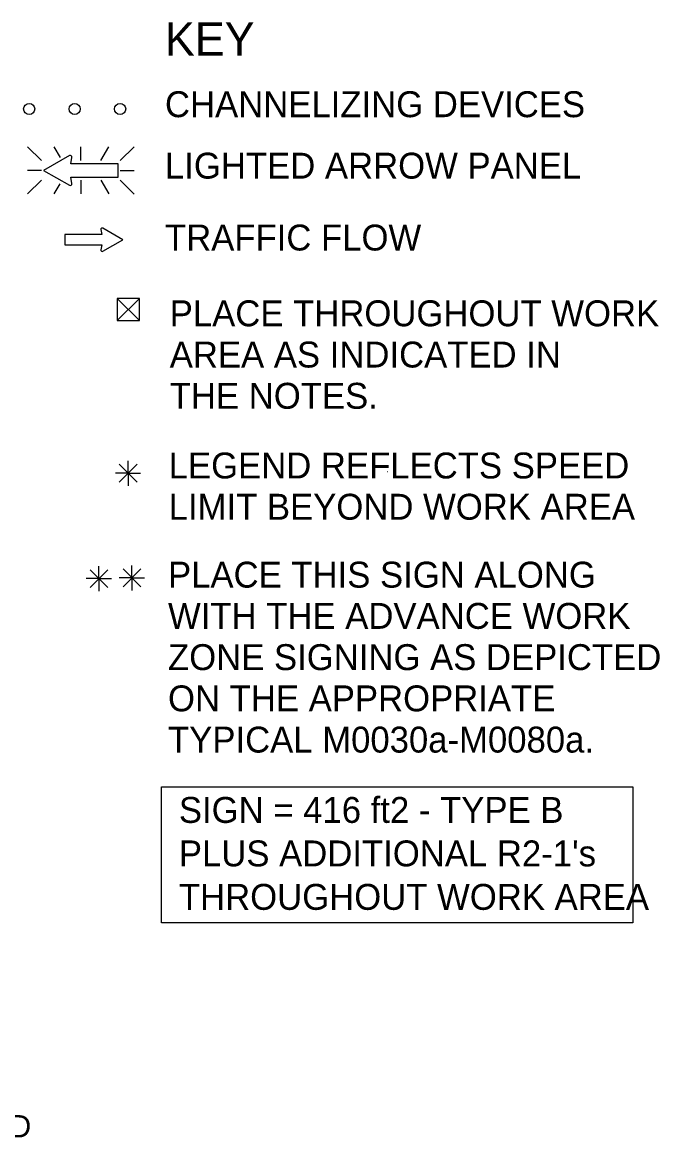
# Model space of a CAD drawing. Extents: x 16489 to 18480, y 5759 to 7026.
# Drawn here: x 17180.5 to 17409, y 6524.1 to 6924.4 of the extents above; entities that cross this region are included whole.
import ezdxf

# ---------------------------------------------------------------- set-up
doc = ezdxf.new("R2010")
doc.units = 0
for name, color, linetype in [('MT_SCRATCH_LEVEL_E', 7, 'Continuous'), ('TRAFFIC_SIGNS_PR', 7, 'Continuous'), ('TYPICAL_TEXT_DIMEN_EX', 7, 'Continuous'), ('TYPICAL_TEXT_DIMEN_PR', 7, 'Continuous')]:
    doc.layers.add(name, color=color, linetype=linetype)

msp = doc.modelspace()

# ---------------------------------------------------------------- linework, layer by layer
at = {"layer": 'MT_SCRATCH_LEVEL_E'}
for p, q in [((17208.65, 6849.99), (17208.96, 6848.21)), ((17216.57, 6846.36), (17209.33, 6850.47)), ((17208.96, 6848.21), (17195.71, 6848.21)), ((17195.71, 6848.21), (17195.71, 6844.47)), ((17209.33, 6842.22), (17216.57, 6846.36)), ((17195.71, 6844.47), (17208.96, 6844.47)), ((17208.96, 6844.47), (17208.65, 6842.69))]:
    msp.add_line(p, q, dxfattribs=at)
for centre, start, end in [((17209.11, 6850.07), 60.4248, 189.9638), ((17209.11, 6842.62), 170.0362, 299.7731)]:
    msp.add_arc(centre, 0.463, start, end, dxfattribs=at)
at = {"layer": 'TRAFFIC_SIGNS_PR'}
for p, q in [((17182.39, 6879.74), (17187.32, 6874.81)), ((17194.15, 6875.92), (17191.94, 6879.75)), ((17201.47, 6874.81), (17201.47, 6879.75)), ((17208.7, 6874.81), (17211.55, 6879.75)), ((17215.62, 6874.81), (17220.55, 6879.75)), ((17187.32, 6871.26), (17182.39, 6871.26)), ((17215.62, 6871.26), (17220.55, 6871.26)), ((17182.39, 6862.77), (17187.32, 6867.7)), ((17191.9, 6862.77), (17194.01, 6866.43)), ((17201.47, 6867.7), (17201.47, 6862.77)), ((17211.6, 6862.77), (17208.75, 6867.7)), ((17215.62, 6867.7), (17220.55, 6862.76))]:
    msp.add_line(p, q, dxfattribs=at)
for points in [[(17197.4, 6876.53), (17188.1, 6871.26), (17197.4, 6865.94)], [(17198.27, 6866.56), (17197.87, 6868.83), (17214.88, 6868.83), (17214.88, 6873.63), (17197.87, 6873.63), (17198.27, 6875.91)]]:
    msp.add_lwpolyline(points, dxfattribs=at)
for centre in [(17182.95, 6893.29), (17199.25, 6893.29), (17215.55, 6893.29)]:
    msp.add_circle(centre, 2, dxfattribs=at)
for centre, radius, start, end in [((17197.68, 6876.01), 0.598, 350.7308, 118.8916), ((17197.68, 6866.46), 0.597, 241.4833, 9.9593)]:
    msp.add_arc(centre, radius, start, end, dxfattribs=at)
at = {"layer": 'TYPICAL_TEXT_DIMEN_EX'}
msp.add_lwpolyline([(17230.4, 6650.05), (17399.41, 6650.05), (17399.41, 6601.22), (17230.4, 6601.22)], close=True, dxfattribs=at)
at = {"layer": 'TYPICAL_TEXT_DIMEN_PR'}
for p, q in [((17214.46, 6825.32), (17222.46, 6817.32)), ((17214.46, 6817.32), (17222.46, 6825.32)), ((17221.61, 6765.77), (17215.23, 6759.39)), ((17215.24, 6765.77), (17221.61, 6759.39)), ((17218.42, 6762.58), (17218.42, 6767.04)), ((17218.42, 6762.58), (17213.89, 6762.58)), ((17218.42, 6762.58), (17221.61, 6762.58)), ((17218.42, 6762.58), (17222.9, 6762.58)), ((17218.42, 6762.58), (17218.42, 6758.08)), ((17207.95, 6724.75), (17207.95, 6729.21)), ((17219.79, 6725.01), (17219.79, 6729.47)), ((17204.77, 6727.94), (17211.14, 6721.56)), ((17211.14, 6727.94), (17204.77, 6721.56)), ((17219.79, 6725.01), (17215.26, 6725.01)), ((17216.6, 6728.2), (17222.98, 6721.83)), ((17222.98, 6728.2), (17216.6, 6721.83)), ((17219.79, 6725.01), (17222.98, 6725.01)), ((17219.79, 6725.01), (17224.27, 6725.01)), ((17219.79, 6725.01), (17219.79, 6720.51)), ((17207.95, 6724.75), (17203.42, 6724.75)), ((17207.95, 6724.75), (17211.14, 6724.75)), ((17207.95, 6724.75), (17212.43, 6724.75)), ((17207.95, 6724.75), (17207.95, 6720.25))]:
    msp.add_line(p, q, dxfattribs=at)
msp.add_lwpolyline([(17214.46, 6825.32), (17214.46, 6817.32), (17222.46, 6817.32), (17222.46, 6825.32)], close=True, dxfattribs=at)
msp.add_open_spline([(17311.37, 6763.17), (17311.39, 6763.17), (17311.4, 6763.17), (17311.4, 6763.17)], degree=2, dxfattribs=at)

# ---------------------------------------------------------------- texts
at = {"layer": 'TRAFFIC_SIGNS_PR'}
msp.add_text('SPEED', height=8.01, dxfattribs=at).set_placement((17147.36, 6524.21))
at = {"layer": 'TYPICAL_TEXT_DIMEN_EX'}
for s, height, p in [('KEY', 12, (17231.64, 6912.39)), ('CHANNELIZING DEVICES', 9.3, (17231.64, 6890.34)), ('LIGHTED ARROW PANEL', 9.3, (17231.64, 6868.29)), ('TRAFFIC FLOW', 9.3, (17231.64, 6842.49)), ('PLACE THROUGHOUT WORK', 9.3, (17233.35, 6815.3)), ('AREA AS INDICATED IN', 9.3, (17233.35, 6800.5)), ('THE NOTES.', 9.3, (17233.35, 6785.7)), ('LEGEND REFLECTS SPEED', 9.3, (17232.97, 6760.68)), ('LIMIT BEYOND WORK AREA', 9.3, (17232.97, 6745.88)), ('PLACE THIS SIGN ALONG', 9.3, (17232.73, 6721.51)), ('WITH THE ADVANCE WORK', 9.3, (17232.73, 6706.71)), ('ZONE SIGNING AS DEPICTED', 9.3, (17232.73, 6691.91)), ('ON THE APPROPRIATE', 9.3, (17232.73, 6677.11)), ('TYPICAL M0030a-M0080a.', 9.3, (17232.73, 6662.31)), ('SIGN = 416 ft2 - TYPE B', 9.3, (17236.63, 6637.07)), ("PLUS ADDITIONAL R2-1's", 9.3, (17236.63, 6621.47)), ('THROUGHOUT WORK AREA', 9.3, (17236.63, 6605.87))]:
    msp.add_text(s, height=height, dxfattribs=at).set_placement(p)

doc.saveas('drawing.dxf')
